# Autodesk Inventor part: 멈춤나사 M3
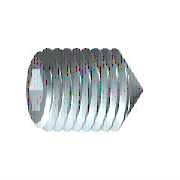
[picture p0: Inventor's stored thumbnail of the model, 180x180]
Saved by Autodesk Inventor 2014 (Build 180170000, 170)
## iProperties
IsCustomPart: 1
Created: 2012-02
Part Number: 멈춤나사 M3
Material: 강철, 연강
Description: 6각 소켓 머리 없는 멈춤 나사
Document SubType Name: Modeling
Standard: KS B 1028
Designer: test
Standards Organization: KS
Language: ko-KR
Size Designation: 원추점 M3x8
Categories: <MemberInstance><Categories><Category DisplayName="조임쇠" InternalName="e4da775c-781d-43d5-af7c-5136215cf5a6" Mnemonic="FSTN"><Category DisplayName="볼트" InternalN
Density: 1 g/cm^3
Appearance: Steel
Author: test
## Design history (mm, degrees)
sketch "스케치1"
  geometry: L1 (0, 0)-(5.5, 0); L2 (8, 0.866)-(8, 1.5); L3 (8, 1.5)-(0, 1.5); L4 (8, 0.866)-(6, 0.866); L5 (6, 0.866)-(5.5, 0); L6 (0, -0.3)-(0, 1.8) reference; L7 (0, 1.5)-(0, 0)
  constraints: 13 end point, 3 parallel, 1 collinear, 1 perpendicular, 1 point on line
  dimensions: "d0" = 2 distance of L2.start L4.end (= INTI); "d1" = 60 deg angle of L5 L1; "d2" = 3 diameter of L3 L1 (= NND); "d3" = 1.73205 diameter of L4 L1 (= 1.1547 x SW); "d5" = 8 distance from line of L2 L3.end (= NLG)
revolve "본체" sketch "스케치1" stored, may be unused: angle "d6" = 90 deg
sketch "스케치2"
  geometry: L1 (-0.433, 0.75)-(0.433, 0.75); L2 (0.433, 0.75)-(0.866, 0); L3 (0.866, 0)-(0.433, -0.75); L4 (0.433, -0.75)-(-0.433, -0.75); L5 (-0.433, -0.75)-(-0.866, 0); L6 (-0.866, 0)-(-0.433, 0.75); 3 further points
  constraints: 12 end point, 1 coincident, 1 horizontal, 13 other
extrude "슬롯" join sketch "스케치2" taper "d7" = 0 deg; stored distance "d21" = 10
workaxis "Work Axis1"
workplane "Work Plane1"
sketch "스케치4"
  geometry: L1 (0, 0.15)-(-1.35, 1.5) reference; L2 (0, -0.15)-(-1.35, -1.5) reference; L3 (-1.35, -1.5)-(0.15, 0); L4 (-1.35, 1.5)-(0.15, 0); 2 further points
  constraints: 4 end point, 1 coincident, 1 collinear, 1 horizontal alignment
workpoint "Work Point2"
  workaxis "Work Axis2"
body "Solid1"
feature "스레드" dims "d12" = 8 (= NLG), "d13" = 0
chamfer "모따기1" distance "d8" = 1.35 (computed from NND, SPD, FAWI); stored, may be unused: angle "d9" = 45 deg (= FAWI), second distance "d34" = 1.35 (computed from NND, SPD, FAWI)
chamfer "모따기2" distance "d10" = 0.30673 (= -0.5 x GD1 + 0.5 x NND); stored, may be unused: angle "d11" = 45 deg (= FAWI), second distance "d35" = 0.30673 (= -0.5 x GD1 + 0.5 x NND)
other parameters: "NND" = 3 [user parameter; used in 5 equation terms], "NLG" = 8 [user parameter; used in 2 equation terms], "INTI" = 2 [user parameter; used in 1 equation term], "FAWI" = 45 deg [user parameter; used in 4 equation terms], "SW" = 1.5 [user parameter; used in 2 equation terms], "GD1" = 2.38655 (= THREADDIA - 1.2269 x PTC) [user parameter; used in 2 equation terms], "d4" = 0, "FAWI1" = 45 deg [user parameter], "SPD" = 0.3 [user parameter; used in 2 equation terms], "d36" = 0, "d37" = 0, "GUL" = 0.30673 (= 0.61345 x PTC) [user parameter], "TOA" = 30 deg [user parameter], "THREADDIA" = 3 [user parameter; used in 1 equation term], "PTC" = 0.5 [user parameter; used in 4 equation terms], "GAL" = 0.30673 (= 0.61345 x PTC) [user parameter], "E0" = 1.7325 (= 1.155 x SW) [user parameter]
